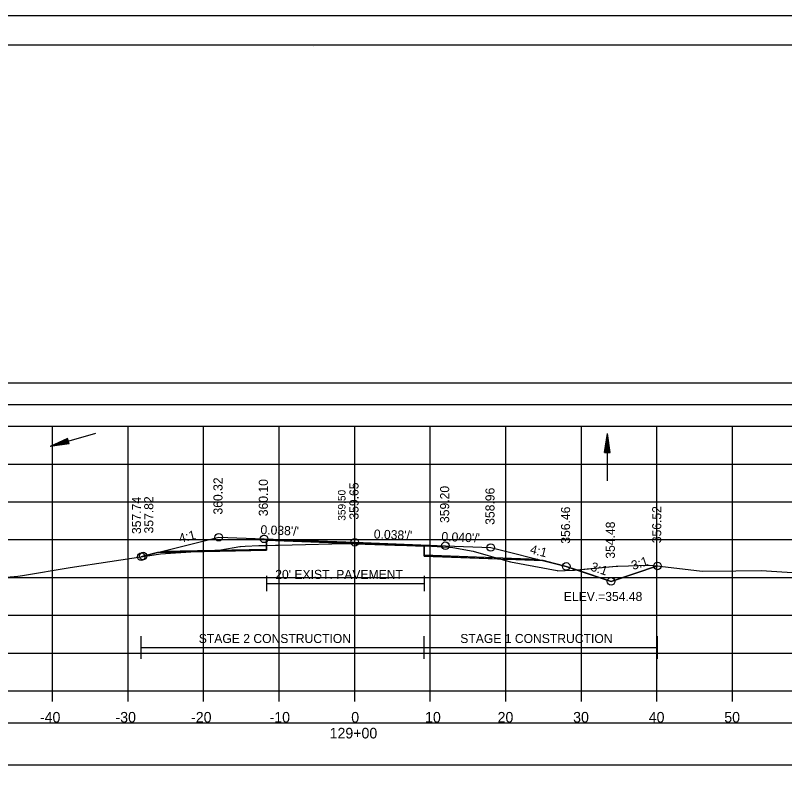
# Model space of a CAD drawing. Extents: x 1376273 to 1384221, y 378927 to 384592.
# Drawn here: x 1377012.9 to 1377114.7, y 381077 to 381178.5 of the extents above; entities that cross this region are included whole.
import ezdxf

# ---------------------------------------------------------------- set-up
doc = ezdxf.new("R2010")
doc.units = 0
for name, color, linetype in [('R_Alt Surface', 7, 'Continuous'), ('R_Axis', 7, 'Continuous'), ('R_Axis Annot', 7, 'Continuous'), ('R_Border', 7, 'Continuous'), ('R_Border Notes', 7, 'Continuous'), ('R_Dimension', 7, 'Continuous'), ('R_Exist Surface', 7, 'Continuous'), ('R_Fin Surface', 7, 'Continuous'), ('R_Grid', 7, 'Continuous'), ('R_No Plot', 7, 'Continuous'), ('R_Water', 7, 'Continuous'), ('R_Xsect Elev', 7, 'Continuous'), ('R_Xsect Slope', 7, 'Continuous'), ('T_Detection Zones', 7, 'Continuous'), ('T_Vehicle Path Lt Minor', 7, 'Continuous')]:
    doc.layers.add(name, color=color, linetype=linetype)

msp = doc.modelspace()

# ---------------------------------------------------------------- linework, layer by layer
at = {"layer": 'R_Alt Surface'}
for points in [[(1377032.38, 381107.65), (1377046.09, 381107.92), (1377046.1, 381109.09), (1377057.77, 381108.65), (1377066.94, 381108.31), (1377066.95, 381107.14), (1377082, 381106.57)], [(1377046.1, 381104.36), (1377046.1, 381102.36)], [(1377066.94, 381104.36), (1377066.94, 381102.36)], [(1377046.1, 381103.36), (1377066.94, 381103.36)]]:
    msp.add_lwpolyline(points, dxfattribs=at)
at = {"layer": 'R_Axis'}
for p, q in [((1376907.77, 381089.17), (1377207.77, 381089.17)), ((1377017.77, 381087.77), (1377017.77, 381089.17)), ((1377027.77, 381087.77), (1377027.77, 381089.17)), ((1377037.77, 381087.77), (1377037.77, 381089.17)), ((1377047.77, 381087.77), (1377047.77, 381089.17)), ((1377057.77, 381087.77), (1377057.77, 381089.17)), ((1377067.77, 381087.77), (1377067.77, 381089.17)), ((1377077.77, 381087.77), (1377077.77, 381089.17)), ((1377087.77, 381087.77), (1377087.77, 381089.17)), ((1377097.77, 381087.77), (1377097.77, 381089.17)), ((1377107.77, 381087.77), (1377107.77, 381089.17))]:
    msp.add_line(p, q, dxfattribs=at)
at = {"layer": 'R_Axis Annot'}
for points in [[(1376907.2, 381127.04), (1377209.01, 381127.04), (1377209.01, 381129.86), (1376907.2, 381129.86)], [(1376907.2, 381079.36), (1377209.01, 381079.36), (1377209.01, 381084.89), (1376907.2, 381084.89)]]:
    msp.add_lwpolyline(points, close=True, dxfattribs=at)
at = {"layer": 'R_Border'}
for p, q in [((1376899.77, 381174.63), (1377215.95, 381174.63)), ((1377052.29, 381174.37), (1377052.29, 381174.37)), ((1377052.29, 381174.37), (1377052.29, 381174.37))]:
    msp.add_line(p, q, dxfattribs=at)
at = {"layer": 'R_Dimension'}
for p, q in [((1377029.51, 381093.39), (1377029.51, 381096.39)), ((1377066.94, 381093.39), (1377066.94, 381096.39)), ((1377097.84, 381093.39), (1377097.84, 381096.39)), ((1377029.51, 381094.89), (1377097.84, 381094.89))]:
    msp.add_line(p, q, dxfattribs=at)
at = {"layer": 'R_Exist Surface'}
msp.add_lwpolyline([(1376994.6, 381102.69), (1377013.17, 381104.35), (1377013.49, 381104.38), (1377013.81, 381104.43), (1377020.09, 381105.5), (1377025.35, 381106.29), (1377032.07, 381107.29), (1377038.56, 381107.73), (1377040.07, 381107.83), (1377042.58, 381108.25), (1377042.62, 381108.25), (1377042.63, 381108.26), (1377043.26, 381108.29), (1377045.1, 381108.38), (1377049.51, 381108.49), (1377056.5, 381108.67), (1377063.06, 381108.45), (1377067.94, 381108.29), (1377067.96, 381108.29), (1377070.14, 381108.18), (1377070.75, 381108.14), (1377070.76, 381108.14), (1377073.44, 381107.64), (1377077.71, 381106.42), (1377078.4, 381106.22), (1377084.55, 381105.08), (1377084.65, 381105.06), (1377084.67, 381105.06), (1377086.6, 381105.13), (1377086.84, 381105.15), (1377092.36, 381105.68), (1377092.58, 381105.68), (1377096.78, 381105.81), (1377098.16, 381105.66), (1377103.75, 381104.99), (1377108.23, 381105.06), (1377111.58, 381105.09), (1377118.44, 381104.66)], dxfattribs=at)
at = {"layer": 'R_Fin Surface'}
msp.add_lwpolyline([(1377029.51, 381106.91), (1377029.77, 381106.99), (1377031.67, 381107.47), (1377039.77, 381109.49), (1377045.77, 381109.27), (1377057.77, 381108.82), (1377069.77, 381108.37), (1377075.77, 381108.13), (1377084.22, 381106.01), (1377085.77, 381105.63), (1377091.7, 381103.65), (1377097.84, 381105.69)], dxfattribs=at)
at = {"layer": 'R_Grid'}
for p, q in [((1376907.77, 381124.17), (1377207.77, 381124.17)), ((1376907.77, 381124.17), (1377207.77, 381124.17)), ((1377017.77, 381089.17), (1377017.77, 381124.17)), ((1377017.77, 381089.17), (1377017.77, 381124.17)), ((1377027.77, 381089.17), (1377027.77, 381124.17)), ((1377027.77, 381089.17), (1377027.77, 381124.17)), ((1377037.77, 381089.17), (1377037.77, 381124.17)), ((1377037.77, 381089.17), (1377037.77, 381124.17)), ((1377047.77, 381089.17), (1377047.77, 381124.17)), ((1377047.77, 381089.17), (1377047.77, 381124.17)), ((1377057.77, 381089.17), (1377057.77, 381124.17)), ((1377057.77, 381089.17), (1377057.77, 381124.17)), ((1377067.77, 381089.17), (1377067.77, 381124.17)), ((1377067.77, 381089.17), (1377067.77, 381124.17)), ((1377077.77, 381089.17), (1377077.77, 381124.17)), ((1377077.77, 381089.17), (1377077.77, 381124.17)), ((1377087.77, 381089.17), (1377087.77, 381124.17)), ((1377087.77, 381089.17), (1377087.77, 381124.17)), ((1377097.77, 381089.17), (1377097.77, 381124.17)), ((1377097.77, 381089.17), (1377097.77, 381124.17)), ((1377107.77, 381089.17), (1377107.77, 381124.17)), ((1377107.77, 381089.17), (1377107.77, 381124.17)), ((1376907.77, 381119.17), (1377207.77, 381119.17)), ((1376907.77, 381119.17), (1377207.77, 381119.17)), ((1376907.77, 381114.17), (1377207.77, 381114.17)), ((1376907.77, 381114.17), (1377207.77, 381114.17)), ((1376907.77, 381109.17), (1377207.77, 381109.17)), ((1376907.77, 381109.17), (1377207.77, 381109.17)), ((1376907.77, 381104.17), (1377207.77, 381104.17)), ((1376907.77, 381104.17), (1377207.77, 381104.17)), ((1376907.77, 381099.17), (1377207.77, 381099.17)), ((1376907.77, 381099.17), (1377207.77, 381099.17)), ((1376907.77, 381094.17), (1377207.77, 381094.17)), ((1376907.77, 381094.17), (1377207.77, 381094.17)), ((1376907.77, 381089.17), (1377207.77, 381089.17)), ((1376907.77, 381089.17), (1377207.77, 381089.17))]:
    msp.add_line(p, q, dxfattribs=at)
at = {"layer": 'R_No Plot'}
msp.add_line((1376887.37, 381178.52), (1377220.7, 381178.52), dxfattribs=at)
for points in [[(1376887.36, 381178.52), (1377220.7, 381178.52), (1377220.7, 380965.19), (1376887.36, 380965.19)], [(1377133.69, 381174.63), (1377133.69, 381164.75), (1377169.42, 381164.75), (1377169.42, 381161.83), (1377192.62, 381161.83), (1377192.62, 381137.5), (1377215.95, 381137.5), (1377215.95, 380969.17), (1376899.77, 380969.17), (1376899.77, 381174.63)]]:
    msp.add_lwpolyline(points, close=True, dxfattribs=at)
msp.add_lwpolyline([(1377031.67, 381107.47), (1377046.09, 381107.76), (1377046.1, 381109.09), (1377057.77, 381108.65), (1377066.94, 381108.31), (1377066.95, 381106.98), (1377082.72, 381106.39)], dxfattribs=at)
for centre in [(1377039.77, 381109.49), (1377039.77, 381109.49), (1377045.77, 381109.27), (1377045.77, 381109.27), (1377057.77, 381108.82), (1377057.77, 381108.82), (1377069.77, 381108.37), (1377069.77, 381108.37), (1377075.77, 381108.13), (1377075.77, 381108.13), (1377029.77, 381106.99), (1377029.77, 381106.99), (1377029.51, 381106.91), (1377029.51, 381106.91), (1377085.77, 381105.63), (1377085.77, 381105.63), (1377097.84, 381105.69), (1377097.84, 381105.69), (1377091.7, 381103.65), (1377091.7, 381103.65), (1377091.7, 381103.65), (1377091.7, 381103.65)]:
    msp.add_circle(centre, 0.5, dxfattribs=at)
at = {"layer": 'R_Water'}
for p, q in [((1377023.48, 381123.21), (1377017.47, 381121.51)), ((1377090.84, 381120.71), (1377091.22, 381123.21)), ((1377090.9, 381120.71), (1377091.22, 381122.79)), ((1377091.22, 381116.96), (1377091.22, 381123.21)), ((1377091.59, 381120.71), (1377091.22, 381123.21)), ((1377091.53, 381120.71), (1377091.22, 381122.79)), ((1377019.77, 381122.55), (1377017.47, 381121.51)), ((1377019.97, 381121.83), (1377017.47, 381121.51)), ((1377019.79, 381122.49), (1377017.87, 381121.62)), ((1377019.96, 381121.89), (1377017.87, 381121.62)), ((1377019.81, 381122.43), (1377018.28, 381121.74)), ((1377019.94, 381121.95), (1377018.28, 381121.74)), ((1377019.82, 381122.37), (1377018.68, 381121.85)), ((1377019.92, 381122.01), (1377018.68, 381121.85)), ((1377019.84, 381122.31), (1377019.09, 381121.97)), ((1377019.91, 381122.07), (1377019.09, 381121.97)), ((1377019.86, 381122.24), (1377019.49, 381122.08)), ((1377019.89, 381122.13), (1377019.49, 381122.08)), ((1377019.97, 381121.83), (1377019.77, 381122.55)), ((1377090.97, 381120.71), (1377091.22, 381122.36)), ((1377091.03, 381120.71), (1377091.22, 381121.94)), ((1377091.47, 381120.71), (1377091.22, 381122.36)), ((1377091.4, 381120.71), (1377091.22, 381121.94)), ((1377090.84, 381120.71), (1377091.59, 381120.71)), ((1377091.1, 381120.71), (1377091.22, 381121.52)), ((1377091.16, 381120.71), (1377091.22, 381121.1)), ((1377091.34, 381120.71), (1377091.22, 381121.52)), ((1377091.28, 381120.71), (1377091.22, 381121.1))]:
    msp.add_line(p, q, dxfattribs=at)
at = {"layer": 'T_Detection Zones'}
for points in [[(1377029.51, 381106.91), (1377032.07, 381107.29), (1377036.06, 381107.56), (1377031.67, 381107.47), (1377029.77, 381106.99)], [(1377036.06, 381107.56), (1377038.56, 381107.73), (1377040.07, 381107.83), (1377042.58, 381108.25), (1377042.62, 381108.25), (1377042.63, 381108.26), (1377043.26, 381108.29), (1377045.1, 381108.38), (1377046.1, 381108.41), (1377046.09, 381107.76)], [(1377062.85, 381108.46), (1377063.06, 381108.45), (1377067.94, 381108.29), (1377067.96, 381108.29), (1377070.14, 381108.18), (1377070.75, 381108.14), (1377070.76, 381108.14), (1377073.44, 381107.64), (1377077.1, 381106.6), (1377066.95, 381106.98), (1377066.94, 381108.31)], [(1377077.1, 381106.6), (1377077.71, 381106.42), (1377078.4, 381106.22), (1377084.55, 381105.08), (1377084.65, 381105.06), (1377084.67, 381105.06), (1377086.6, 381105.13), (1377086.84, 381105.15), (1377087.11, 381105.18), (1377085.77, 381105.63), (1377084.22, 381106.01), (1377082.72, 381106.39)], [(1377087.11, 381105.18), (1377092.36, 381105.68), (1377092.58, 381105.68), (1377096.78, 381105.81), (1377097.84, 381105.69), (1377091.7, 381103.65)]]:
    msp.add_lwpolyline(points, close=True, dxfattribs=at)
at = {"layer": 'T_Vehicle Path Lt Minor'}
msp.add_lwpolyline([(1377046.1, 381108.41), (1377049.51, 381108.49), (1377056.5, 381108.67), (1377062.85, 381108.46), (1377057.77, 381108.65), (1377046.1, 381109.09)], close=True, dxfattribs=at)

# ---------------------------------------------------------------- texts
at = {"layer": 'R_Alt Surface'}
msp.add_text("20' EXIST. PAVEMENT", height=1.2, dxfattribs=at).set_placement((1377047.25, 381103.97))
at = {"layer": 'R_Axis Annot'}
for s, p in [('-40', (1377016.11, 381084.97)), ('-30', (1377026.11, 381084.97)), ('-20', (1377036.11, 381084.97)), ('-10', (1377046.5, 381084.97)), ('0', (1377057.31, 381084.97)), ('10', (1377067.08, 381084.97)), ('20', (1377076.68, 381084.97)), ('30', (1377086.68, 381084.97)), ('40', (1377096.68, 381084.97)), ('50', (1377106.68, 381084.97)), ('129+00', (1377054.45, 381082.87))]:
    msp.add_text(s, height=1.4, dxfattribs=at).set_placement(p)
at = {"layer": 'R_Border Notes'}
msp.add_text('ELEV.=354.48', height=1.2, dxfattribs=at).set_placement((1377085.44, 381101.05))
at = {"layer": 'R_Dimension'}
for s, p in [('STAGE 2 CONSTRUCTION', (1377037.13, 381095.49)), ('STAGE 1 CONSTRUCTION', (1377071.74, 381095.49))]:
    msp.add_text(s, height=1.2, dxfattribs=at).set_placement(p)
at = {"layer": 'R_No Plot'}
for s, p in [('360.32', (1377040.27, 381112.49)), ('360.10', (1377046.27, 381112.27)), ('359.65', (1377058.27, 381111.82)), ('359.20', (1377070.27, 381111.37)), ('358.96', (1377076.27, 381111.13)), ('357.74', (1377029.49, 381109.91)), ('357.82', (1377031.11, 381109.99)), ('356.46', (1377086.27, 381108.63)), ('356.52', (1377098.34, 381108.69))]:
    msp.add_text(s, height=1.2, rotation=90, dxfattribs=at).set_placement(p)
at = {"layer": 'R_Xsect Elev'}
for s, height, p in [('359.50', 1, (1377056.55, 381111.67)), ('354.48', 1.2, (1377092.2, 381106.65))]:
    msp.add_text(s, height=height, rotation=90, dxfattribs=at).set_placement(p)
at = {"layer": 'R_Xsect Slope'}
for s, rotation, p in [("0.038'/'", 357.8472, (1377045.28, 381109.89)), ("0.038'/'", 357.8472, (1377060.28, 381109.32)), ('4:1', 14.0362, (1377034.65, 381108.73)), ("0.040'/'", 357.7094, (1377069.23, 381108.99)), ('4:1', 345.9638, (1377080.89, 381107.36)), ('3:1', 18.4349, (1377094.61, 381105.14)), ('3:1', 341.5651, (1377088.89, 381105.11))]:
    msp.add_text(s, height=1.2, rotation=rotation, dxfattribs=at).set_placement(p)

doc.saveas('drawing.dxf')
